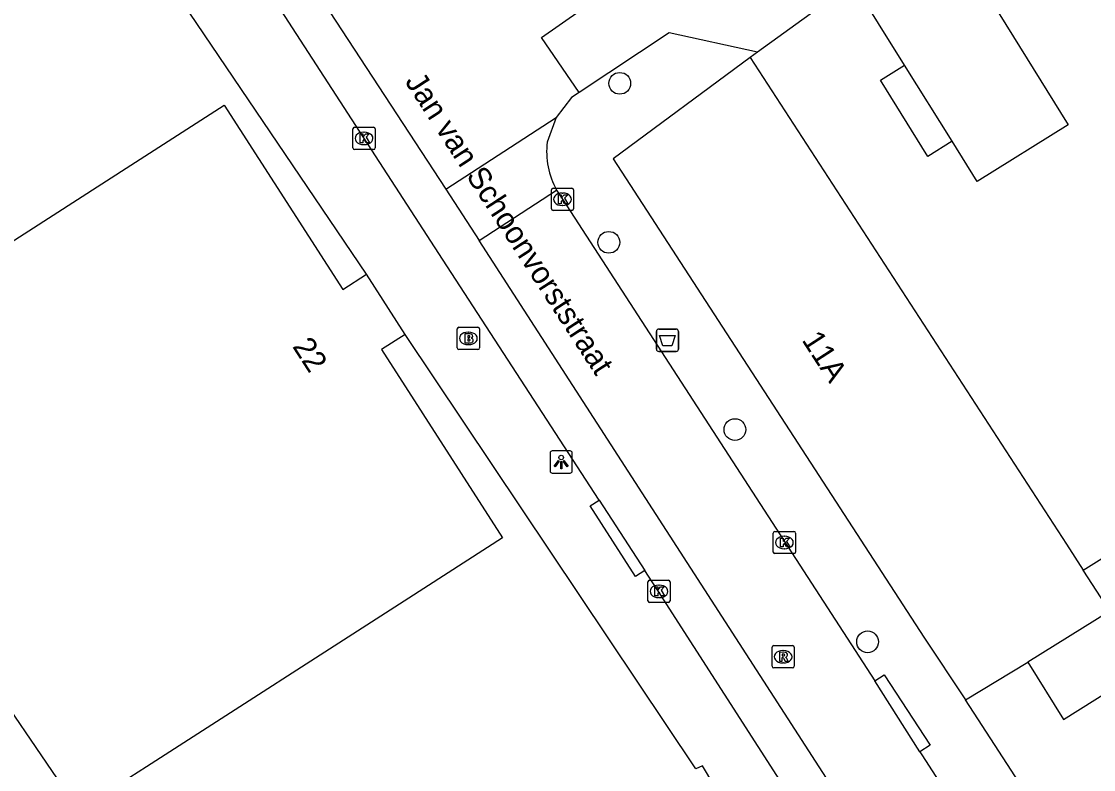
# Model space of a CAD drawing. Extents: x 161801 to 162379, y 382315 to 382832.
# Drawn here: x 161894.26 to 161942.5, y 382516.53 to 382550.17 of the extents above; entities that cross this region are included whole.
import ezdxf

# ---------------------------------------------------------------- set-up
doc = ezdxf.new("R2010")
doc.units = 0
for name, color, linetype in [('IMGEO_Afvalbak', 7, 'Continuous'), ('IMGEO_Boom', 7, 'Continuous'), ('IMGEO_Brandkraan', 7, 'Continuous'), ('IMGEO_Kolk', 7, 'Continuous'), ('IMGEO_Lichtpunt', 7, 'Continuous'), ('IMGEO_Openbare_ruimte_label', 7, 'Continuous'), ('IMGEO_Pand', 7, 'Continuous'), ('IMGEO_Pand_nummerreeks', 7, 'Continuous'), ('IMGEO_Rijbaan_lokaal_open', 7, 'Continuous'), ('IMGEO_Rioolput', 7, 'Continuous'), ('IMGEO_Voetpad_open', 7, 'Continuous')]:
    doc.layers.add(name, color=color, linetype=linetype)

msp = doc.modelspace()

# ---------------------------------------------------------------- linework, layer by layer
at = {"layer": 'IMGEO_Afvalbak'}
for p, q in [((161922.83, 382535.436), (161922.83, 382536.236)), ((161922.83, 382536.236), (161922.83, 382535.436)), ((161922.93, 382536.336), (161923.72, 382536.336)), ((161923.72, 382536.336), (161922.93, 382536.336)), ((161923.82, 382536.236), (161923.82, 382535.436)), ((161923.82, 382535.436), (161923.82, 382536.236)), ((161923.72, 382535.336), (161922.93, 382535.336)), ((161922.93, 382535.336), (161923.72, 382535.336))]:
    msp.add_line(p, q, dxfattribs=at)
msp.add_lwpolyline([(161922.973, 382536.05), (161923.677, 382536.05), (161923.528, 382535.58), (161923.122, 382535.58), (161922.973, 382536.05)], dxfattribs=at)
for centre, start, end in [((161922.93, 382536.236), 90, 180), ((161922.93, 382536.236), 90, 180), ((161923.72, 382536.236), 0, 90), ((161923.72, 382536.236), 360, 90), ((161922.93, 382535.436), 180, 270), ((161922.93, 382535.436), 180, 270), ((161923.72, 382535.436), 270, 0), ((161923.72, 382535.436), 270, 0)]:
    msp.add_arc(centre, 0.1, start, end, dxfattribs=at)
at = {"layer": 'IMGEO_Boom'}
for centre in [(161921.179, 382547.388), (161920.685, 382540.238), (161926.362, 382531.818), (161932.332, 382522.276)]:
    msp.add_circle(centre, 0.489, dxfattribs=at)
at = {"layer": 'IMGEO_Brandkraan'}
for p, q in [((161913.866, 382535.494), (161913.866, 382536.346)), ((161913.941, 382536.42), (161914.793, 382536.42)), ((161914.867, 382536.346), (161914.867, 382535.494)), ((161914.354, 382536.2), (161914.379, 382536.2)), ((161914.793, 382535.42), (161913.941, 382535.42)), ((161914.377, 382535.64), (161914.352, 382535.64))]:
    msp.add_line(p, q, dxfattribs=at)
for points in [[(161913.866, 382535.494), (161913.866, 382536.346)], [(161913.941, 382536.42), (161914.793, 382536.42)], [(161914.867, 382536.346), (161914.867, 382535.494)], [(161914.214, 382536.12), (161914.214, 382535.72), (161914.427, 382535.72)], [(161914.445, 382536.12), (161914.214, 382536.12)], [(161914.393, 382536.039), (161914.339, 382536.039), (161914.339, 382535.963)], [(161914.339, 382535.963), (161914.392, 382535.963)], [(161914.401, 382535.887), (161914.339, 382535.887), (161914.339, 382535.806)], [(161914.793, 382535.42), (161913.941, 382535.42)], [(161914.339, 382535.806), (161914.401, 382535.806)]]:
    msp.add_lwpolyline(points, dxfattribs=at)
for centre, radius, start, end in [((161913.943, 382536.344), 0.0765, 91.552, 178.448), ((161913.943, 382536.344), 0.0765, 91.552, 178.448), ((161914.791, 382536.344), 0.0765, 1.552, 88.448), ((161914.791, 382536.344), 0.0765, 1.552, 88.448), ((161914.394, 382536.001), 0.0379, 267.8285, 90.9355), ((161914.402, 382535.846), 0.0404, 269.8759, 90.5077), ((161914.449, 382535.975), 0.145, 59.4692, 91.5367), ((161914.474, 382536.022), 0.0922, 285.5137, 58.1501), ((161914.479, 382535.83), 0.105, 301.3115, 78.989), ((161913.943, 382535.496), 0.0765, 181.552, 268.448), ((161913.943, 382535.496), 0.0765, 181.552, 268.448), ((161914.433, 382535.971), 0.251, 268.6676, 293.5347), ((161914.791, 382535.496), 0.0765, 271.552, 358.448), ((161914.791, 382535.496), 0.0765, 271.552, 358.448)]:
    msp.add_arc(centre, radius, start, end, dxfattribs=at)
for centre, major_axis, ratio, start_param, end_param in [((161914.353, 382535.92), (-0.387, 0.002), 0.722429, 4.712389, 7.853982), ((161914.378, 382535.92), (-0.39, 0.002), 0.717154, 1.570796, 4.712389)]:
    msp.add_ellipse(centre, major_axis=major_axis, ratio=ratio, start_param=start_param, end_param=end_param, dxfattribs=at)
at = {"layer": 'IMGEO_Kolk'}
for p, q in [((161909.171, 382544.487), (161909.171, 382545.339)), ((161909.246, 382545.413), (161910.098, 382545.413)), ((161909.659, 382545.193), (161909.684, 382545.193)), ((161910.172, 382545.339), (161910.172, 382544.487)), ((161909.682, 382544.633), (161909.657, 382544.633)), ((161910.098, 382544.413), (161909.246, 382544.413)), ((161918.176, 382542.673), (161919.028, 382542.673)), ((161918.101, 382541.747), (161918.101, 382542.599)), ((161918.589, 382542.453), (161918.614, 382542.453)), ((161919.102, 382542.599), (161919.102, 382541.747)), ((161919.028, 382541.673), (161918.176, 382541.673)), ((161918.612, 382541.893), (161918.587, 382541.893)), ((161928.16, 382527.24), (161929.012, 382527.24)), ((161928.085, 382526.314), (161928.085, 382527.166)), ((161928.573, 382527.02), (161928.598, 382527.02)), ((161929.086, 382527.166), (161929.086, 382526.314)), ((161929.012, 382526.24), (161928.16, 382526.24)), ((161928.596, 382526.46), (161928.571, 382526.46)), ((161922.442, 382524.118), (161922.442, 382524.97)), ((161922.517, 382525.044), (161923.369, 382525.044)), ((161922.93, 382524.824), (161922.955, 382524.824)), ((161923.443, 382524.97), (161923.443, 382524.118)), ((161923.369, 382524.044), (161922.517, 382524.044)), ((161922.953, 382524.264), (161922.928, 382524.264))]:
    msp.add_line(p, q, dxfattribs=at)
for points in [[(161909.171, 382544.487), (161909.171, 382545.339)], [(161909.246, 382545.413), (161910.098, 382545.413)], [(161909.492, 382545.113), (161909.615, 382545.113), (161909.615, 382544.962), (161909.745, 382545.113), (161909.909, 382545.113), (161909.763, 382544.962), (161909.916, 382544.713), (161909.764, 382544.713), (161909.679, 382544.877), (161909.615, 382544.81), (161909.615, 382544.713), (161909.492, 382544.713), (161909.492, 382545.113)], [(161910.172, 382545.339), (161910.172, 382544.487)], [(161910.098, 382544.413), (161909.246, 382544.413)], [(161918.176, 382542.673), (161919.028, 382542.673)], [(161918.101, 382541.747), (161918.101, 382542.599)], [(161918.422, 382542.373), (161918.545, 382542.373), (161918.545, 382542.222), (161918.675, 382542.373), (161918.839, 382542.373), (161918.693, 382542.222), (161918.846, 382541.973), (161918.694, 382541.973), (161918.609, 382542.137), (161918.545, 382542.07), (161918.545, 382541.973), (161918.422, 382541.973), (161918.422, 382542.373)], [(161919.102, 382542.599), (161919.102, 382541.747)], [(161919.028, 382541.673), (161918.176, 382541.673)], [(161928.16, 382527.24), (161929.012, 382527.24)], [(161928.085, 382526.314), (161928.085, 382527.166)], [(161928.406, 382526.94), (161928.529, 382526.94), (161928.529, 382526.789), (161928.659, 382526.94), (161928.823, 382526.94), (161928.677, 382526.789), (161928.83, 382526.54), (161928.678, 382526.54), (161928.593, 382526.704), (161928.529, 382526.637), (161928.529, 382526.54), (161928.406, 382526.54), (161928.406, 382526.94)], [(161929.086, 382527.166), (161929.086, 382526.314)], [(161929.012, 382526.24), (161928.16, 382526.24)], [(161922.442, 382524.118), (161922.442, 382524.97)], [(161922.517, 382525.044), (161923.369, 382525.044)], [(161923.443, 382524.97), (161923.443, 382524.118)], [(161922.763, 382524.744), (161922.886, 382524.744), (161922.886, 382524.593), (161923.016, 382524.744), (161923.18, 382524.744), (161923.034, 382524.593), (161923.187, 382524.344), (161923.035, 382524.344), (161922.95, 382524.508), (161922.886, 382524.441), (161922.886, 382524.344), (161922.763, 382524.344), (161922.763, 382524.744)], [(161923.369, 382524.044), (161922.517, 382524.044)]]:
    msp.add_lwpolyline(points, dxfattribs=at)
for centre, start, end in [((161909.248, 382545.337), 91.552, 178.448), ((161909.248, 382545.337), 91.552, 178.448), ((161910.096, 382545.337), 1.552, 88.448), ((161910.096, 382545.337), 1.552, 88.448), ((161909.248, 382544.489), 181.552, 268.448), ((161909.248, 382544.489), 181.552, 268.448), ((161910.096, 382544.489), 271.552, 358.448), ((161910.096, 382544.489), 271.552, 358.448), ((161918.178, 382542.597), 91.552, 178.448), ((161918.178, 382542.597), 91.552, 178.448), ((161919.026, 382542.597), 1.552, 88.448), ((161919.026, 382542.597), 1.552, 88.448), ((161918.178, 382541.749), 181.552, 268.448), ((161918.178, 382541.749), 181.552, 268.448), ((161919.026, 382541.749), 271.552, 358.448), ((161919.026, 382541.749), 271.552, 358.448), ((161928.162, 382527.164), 91.552, 178.448), ((161928.162, 382527.164), 91.552, 178.448), ((161929.01, 382527.164), 1.552, 88.448), ((161929.01, 382527.164), 1.552, 88.448), ((161928.162, 382526.316), 181.552, 268.448), ((161928.162, 382526.316), 181.552, 268.448), ((161929.01, 382526.316), 271.552, 358.448), ((161929.01, 382526.316), 271.552, 358.448), ((161922.519, 382524.968), 91.552, 178.448), ((161922.519, 382524.968), 91.552, 178.448), ((161923.367, 382524.968), 1.552, 88.448), ((161923.367, 382524.968), 1.552, 88.448), ((161922.519, 382524.12), 181.552, 268.448), ((161922.519, 382524.12), 181.552, 268.448), ((161923.367, 382524.12), 271.552, 358.448), ((161923.367, 382524.12), 271.552, 358.448)]:
    msp.add_arc(centre, 0.0765, start, end, dxfattribs=at)
for centre, major_axis, ratio, start_param, end_param in [((161909.658, 382544.913), (-0.387, 0.002), 0.722429, 4.712389, 7.853982), ((161909.683, 382544.913), (-0.39, 0.002), 0.717154, 1.570796, 4.712389), ((161918.588, 382542.173), (-0.387, 0.002), 0.722429, 4.712389, 7.853982), ((161918.613, 382542.173), (-0.39, 0.002), 0.717154, 1.570796, 4.712389), ((161928.572, 382526.74), (-0.387, 0.002), 0.722429, 4.712389, 7.853982), ((161928.597, 382526.74), (-0.39, 0.002), 0.717154, 1.570796, 4.712389), ((161922.929, 382524.544), (-0.387, 0.002), 0.722429, 4.712389, 7.853982), ((161922.954, 382524.544), (-0.39, 0.002), 0.717154, 1.570796, 4.712389)]:
    msp.add_ellipse(centre, major_axis=major_axis, ratio=ratio, start_param=start_param, end_param=end_param, dxfattribs=at)
at = {"layer": 'IMGEO_Lichtpunt'}
for p, q in [((161918.044, 382530.766), (161918.044, 382529.959)), ((161918.044, 382530.766), (161918.044, 382529.959)), ((161918.946, 382530.861), (161918.138, 382530.861)), ((161918.946, 382530.861), (161918.138, 382530.861)), ((161919.04, 382529.959), (161919.04, 382530.766)), ((161919.04, 382529.959), (161919.04, 382530.766)), ((161918.138, 382529.865), (161918.946, 382529.865)), ((161918.138, 382529.865), (161918.946, 382529.865))]:
    msp.add_line(p, q, dxfattribs=at)
for points in [[(161918.418, 382530.43), (161918.457, 382530.402), (161918.269, 382530.14), (161918.231, 382530.167), (161918.418, 382530.43)], [(161918.52, 382530.382), (161918.567, 382530.382), (161918.567, 382530.06), (161918.52, 382530.06), (161918.52, 382530.382)], [(161918.63, 382530.402), (161918.668, 382530.429), (161918.855, 382530.167), (161918.816, 382530.139), (161918.63, 382530.402)]]:
    msp.add_lwpolyline(points, dxfattribs=at)
msp.add_circle((161918.543, 382530.564), 0.0994, dxfattribs=at)
for centre, start, end in [((161918.138, 382530.766), 90, 180), ((161918.138, 382530.766), 90, 180), ((161918.946, 382530.766), 0, 90), ((161918.946, 382530.766), 0, 90), ((161918.138, 382529.959), 180, 270), ((161918.138, 382529.959), 180, 270), ((161918.946, 382529.959), 270, 0), ((161918.946, 382529.959), 270, 360)]:
    msp.add_arc(centre, 0.0946, start, end, dxfattribs=at)
at = {"layer": 'IMGEO_Pand'}
for points in [[(161933.996, 382548.209), (161931.654, 382551.965)], [(161937.928, 382551.018), (161941.353, 382545.523), (161937.26, 382542.972), (161936.132, 382544.781)], [(161927.045, 382548.554), (161920.885, 382543.991), (161934.863, 382522.49), (161936.739, 382519.665)], [(161927.045, 382548.554), (161941.278, 382526.66), (161942.03, 382525.503)], [(161936.132, 382544.781), (161935.046, 382544.104), (161932.91, 382547.532), (161933.996, 382548.209)], [(161936.132, 382544.781), (161933.996, 382548.209)], [(161911.526, 382536.099), (161910.458, 382535.413), (161915.897, 382526.946), (161911.691, 382524.244), (161899.885, 382516.66), (161899.137, 382516.18), (161896.844, 382514.707), (161891.795, 382522.077), (161891.059, 382523.15), (161888.906, 382526.293), (161887.039, 382529.019), (161889.755, 382530.763), (161886.621, 382535.643), (161887.378, 382536.128), (161899.179, 382543.71), (161903.381, 382546.409), (161908.71, 382538.113), (161909.788, 382538.805)], [(161911.526, 382536.099), (161909.788, 382538.805)], [(161942.03, 382525.503), (161945.338, 382527.569), (161949.498, 382520.91), (161950.621, 382521.611)], [(161943.233, 382523.653), (161942.03, 382525.503)], [(161943.233, 382523.653), (161939.538, 382521.355)], [(161936.739, 382519.665), (161939.538, 382521.355)], [(161939.538, 382521.355), (161941.143, 382518.786), (161944.848, 382521.101)], [(161944.597, 382507.564), (161936.739, 382519.665)]]:
    msp.add_lwpolyline(points, dxfattribs=at)
at = {"layer": 'IMGEO_Rijbaan_lokaal_open'}
for points in [[(161901.379, 382565.494), (161902.151, 382565.965), (161904.859, 382561.676), (161902.142, 382559.943), (161904.811, 382555.675), (161913.348, 382542.627)], [(161919.354, 382546.979), (161917.654, 382549.445), (161920.339, 382551.345)], [(161919.354, 382546.979), (161919.014, 382546.754), (161918.319, 382545.854)], [(161913.348, 382542.627), (161918.319, 382545.854)], [(161918.319, 382545.854), (161917.915, 382544.747)], [(161913.348, 382542.627), (161914.845, 382540.321)], [(161914.845, 382540.321), (161918.335, 382542.587)], [(161918.335, 382542.587), (161918.599, 382542.176), (161932.663, 382520.514)], [(161932.801, 382512.548), (161914.845, 382540.321)], [(161934.683, 382517.328), (161932.663, 382520.514)], [(161934.683, 382517.328), (161934.769, 382517.192), (161936.334, 382514.781)]]:
    msp.add_lwpolyline(points, dxfattribs=at)
msp.add_arc((161921.471, 382544.318), 3.582, 173.1139, 208.8932, dxfattribs=at)
at = {"layer": 'IMGEO_Rioolput'}
for p, q in [((161928.031, 382521.178), (161928.031, 382522.03)), ((161928.106, 382522.104), (161928.958, 382522.104)), ((161928.519, 382521.884), (161928.544, 382521.884)), ((161929.032, 382522.03), (161929.032, 382521.178)), ((161928.958, 382521.104), (161928.106, 382521.104)), ((161928.542, 382521.324), (161928.517, 382521.324))]:
    msp.add_line(p, q, dxfattribs=at)
for points in [[(161928.031, 382521.178), (161928.031, 382522.03)], [(161928.106, 382522.104), (161928.958, 382522.104)], [(161929.032, 382522.03), (161929.032, 382521.178)], [(161928.62, 382521.802), (161928.368, 382521.804), (161928.368, 382521.404)], [(161928.368, 382521.404), (161928.492, 382521.404), (161928.492, 382521.566), (161928.503, 382521.566)], [(161928.546, 382521.723), (161928.492, 382521.723), (161928.492, 382521.642)], [(161928.492, 382521.642), (161928.544, 382521.642)], [(161928.55, 382521.537), (161928.621, 382521.404), (161928.761, 382521.404), (161928.696, 382521.53)], [(161928.958, 382521.104), (161928.106, 382521.104)]]:
    msp.add_lwpolyline(points, dxfattribs=at)
for centre, radius, start, end in [((161928.108, 382522.028), 0.0765, 91.552, 178.448), ((161928.108, 382522.028), 0.0765, 91.552, 178.448), ((161928.956, 382522.028), 0.0765, 1.552, 88.448), ((161928.956, 382522.028), 0.0765, 1.552, 88.448), ((161928.502, 382521.513), 0.0533, 26.0293, 88.6989), ((161928.528, 382521.831), 0.19, 274.7715, 282.9687), ((161928.552, 382521.627), 0.0964, 77.0061, 93.1865), ((161928.566, 382521.684), 0.0378, 276.6634, 79.6772), ((161928.619, 382521.692), 0.109, 350.3612, 89.416), ((161928.617, 382521.692), 0.112, 277.5842, 350.9817), ((161928.601, 382521.477), 0.108, 29.5134, 73.7905), ((161928.108, 382521.18), 0.0765, 181.552, 268.448), ((161928.108, 382521.18), 0.0765, 181.552, 268.448), ((161928.956, 382521.18), 0.0765, 271.552, 358.448), ((161928.956, 382521.18), 0.0765, 271.552, 358.448)]:
    msp.add_arc(centre, radius, start, end, dxfattribs=at)
for centre, major_axis, ratio, start_param, end_param in [((161928.518, 382521.604), (-0.387, 0.002), 0.722429, 4.712389, 7.853982), ((161928.543, 382521.604), (-0.39, 0.002), 0.717154, 1.570796, 4.712389)]:
    msp.add_ellipse(centre, major_axis=major_axis, ratio=ratio, start_param=start_param, end_param=end_param, dxfattribs=at)
at = {"layer": 'IMGEO_Voetpad_open'}
for points in [[(161920.246, 382528.65), (161913.397, 382539.189), (161900.583, 382558.931), (161897.868, 382563.115), (161899.405, 382564.11), (161901.148, 382565.237)], [(161909.788, 382538.805), (161900.489, 382552.547), (161897.075, 382557.59)], [(161927.849, 382554.013), (161930.015, 382550.687), (161927.378, 382548.793)], [(161927.378, 382548.793), (161923.398, 382549.654), (161919.354, 382546.979)], [(161927.378, 382548.793), (161927.045, 382548.554)], [(161927.077, 382513.05), (161924.902, 382516.697), (161924.608, 382516.565), (161911.526, 382536.099)], [(161922.307, 382525.478), (161921.886, 382525.209), (161919.846, 382528.394), (161920.246, 382528.65)], [(161920.246, 382528.65), (161922.307, 382525.478)], [(161936.464, 382506.883), (161934.984, 382505.994), (161930.297, 382513.067), (161922.992, 382524.425), (161922.307, 382525.478)], [(161932.663, 382520.514), (161933.081, 382520.788), (161935.149, 382517.634), (161934.683, 382517.328)]]:
    msp.add_lwpolyline(points, dxfattribs=at)

# ---------------------------------------------------------------- texts
at = {"layer": 'IMGEO_Openbare_ruimte_label'}
msp.add_text('Jan van Schoonvorststraat', height=1, rotation=303.0383, dxfattribs=at).set_placement((161911.486, 382547.467))
at = {"layer": 'IMGEO_Pand_nummerreeks'}
for s, rotation, p in [('22', 302.8417, (161906.426, 382535.556)), ('11A', 302.9277, (161929.344, 382535.848))]:
    msp.add_text(s, height=1, rotation=rotation, dxfattribs=at).set_placement(p)

doc.saveas('drawing.dxf')
